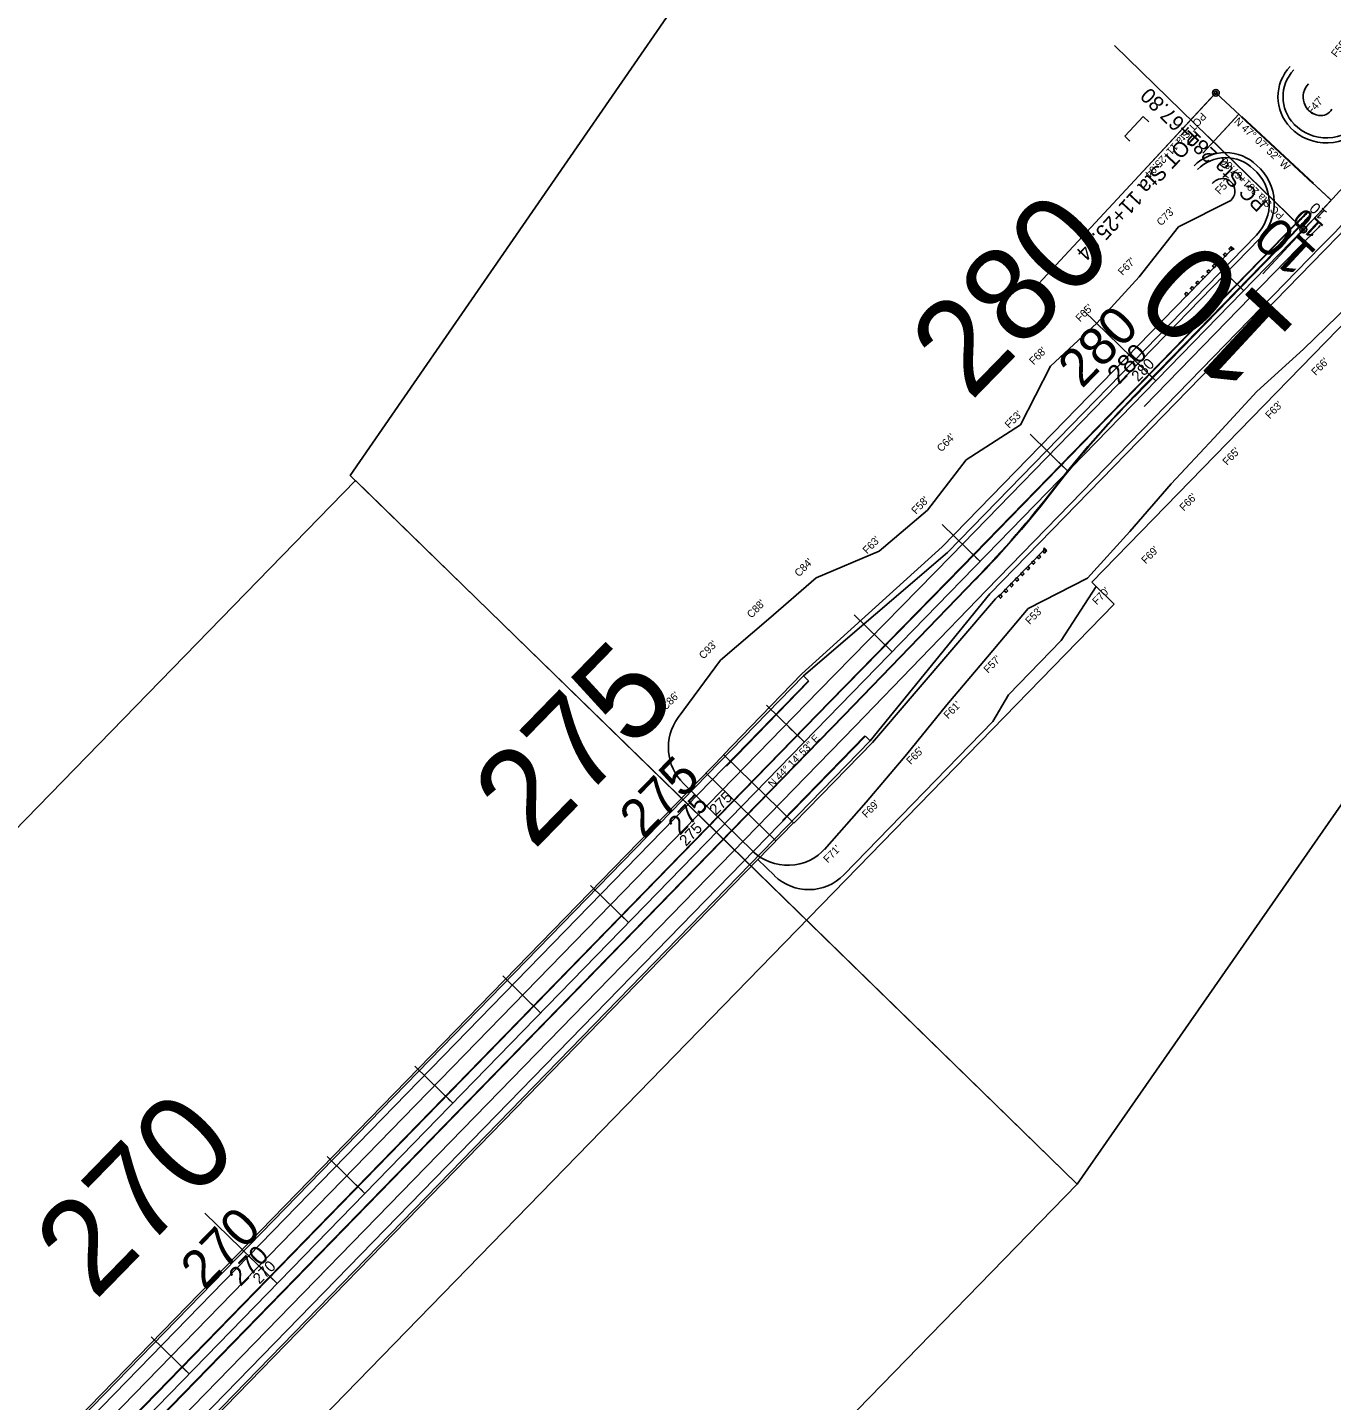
# Model space of a CAD drawing. Extents: x 2358865 to 2362945, y 393485 to 404880.
# Drawn here: x 2360577 to 2361612, y 399070 to 400160 of the extents above; entities that cross this region are included whole.
import ezdxf

# ---------------------------------------------------------------- set-up
doc = ezdxf.new("R2010")
doc.units = 0
for name, color, linetype in [('CL', 7, 'Continuous'), ('Level 11', 7, 'Continuous'), ('Level 12', 7, 'Continuous'), ('Level 19', 7, 'Continuous'), ('Level 21', 7, 'Continuous'), ('Level 25', 7, 'Continuous'), ('Level 27', 7, 'Continuous'), ('Level 28', 7, 'Continuous'), ('Level 30', 7, 'Continuous'), ('Level 33', 7, 'Continuous'), ('Level 35', 7, 'Continuous'), ('Level 36', 7, 'Continuous'), ('Level 37', 7, 'Continuous'), ('Level 39', 7, 'Continuous'), ('Level 41', 7, 'Continuous'), ('Level 48', 7, 'Continuous'), ('Level 50', 7, 'Continuous'), ('Level 51', 7, 'Continuous'), ('Level 52', 7, 'Continuous'), ('Level 53', 7, 'Continuous'), ('Level 58', 7, 'Continuous'), ('Level 59', 7, 'Continuous'), ('Level 63', 7, 'Continuous'), ('PTS-MISC', 7, 'Continuous'), ('STAEQU', 7, 'Continuous')]:
    doc.layers.add(name, color=color, linetype=linetype)

msp = doc.modelspace()

# ---------------------------------------------------------------- linework, layer by layer
at = {"layer": 'CL'}
for p, q in [((2361612.1, 400022.7), (2361520.5, 400107.8)), ((2359688.9, 398047.8), (2361589.9, 399999.4))]:
    msp.add_line(p, q, dxfattribs=at)
msp.add_arc((2360608.6, 400955.3), 1370, 315.7519, 87.327, dxfattribs=at)
at = {"layer": 'Level 11'}
for p, q in [((2361307.5, 399743.1), (2361552.7, 399994.8)), ((2361341.1, 399710.3), (2361606.8, 399983)), ((2361193.1, 399645.1), (2361307.5, 399743.1)), ((2361333.3, 399735.9), (2361333.3, 399735.9)), ((2361246.1, 399593.5), (2361341.1, 399710.3))]:
    msp.add_line(p, q, dxfattribs=at)
for centre, radius, start, end in [((2360608.6, 400955.3), 1346.5, 319.7207, 43.5046), ((2360608.6, 400955.3), 1393.5, 315.7519, 357.7915), ((2361604.8, 400104.6), 31, 136.3969, 224.1653), ((2361608.3, 400108.1), 36, 224.1653, 319.7207), ((2361528.3, 400025.4), 31, 44.7584, 135.8825), ((2361526.9, 400020), 36, 315.7519, 49.3328)]:
    msp.add_arc(centre, radius, start, end, dxfattribs=at)
at = {"layer": 'Level 12'}
for p, q in [((2361533, 399983.2), (2361498.1, 399947.4)), ((2361533, 399983.2), (2361498.1, 399947.4)), ((2361532.2, 399983.9), (2361532.7, 399985.9)), ((2361532.7, 399985.9), (2361535, 399983.8)), ((2361532.7, 399985.7), (2361534.7, 399983.7)), ((2361533, 399983.2), (2361535, 399983.8)), ((2361303.3, 399747.5), (2361498.1, 399947.4)), ((2361191.9, 399646.7), (2361303.3, 399747.5)), ((2361383.7, 399744.7), (2361348.8, 399708.9)), ((2361383.7, 399744.7), (2361348.8, 399708.9)), ((2361383.7, 399744.7), (2361384.2, 399746.8)), ((2361386.1, 399744.5), (2361384.1, 399746.5)), ((2361386.4, 399744.6), (2361384.2, 399746.8)), ((2361384.4, 399744), (2361386.4, 399744.6)), ((2361247.8, 399592.3), (2361345.6, 399706.3)), ((2361345.6, 399706.3), (2361348.4, 399709.2)), ((2361151.3, 399605), (2361191.9, 399646.7)), ((2361151.3, 399605), (2361129.5, 399582.6)), ((2361207.2, 399550.6), (2361247.8, 399592.3)), ((2361185.4, 399528.2), (2361207.2, 399550.6))]:
    msp.add_line(p, q, dxfattribs=at)
for points in [[(2361523.5, 399976.3), (2361522.1, 399974.9), (2361523.5, 399973.5), (2361524.9, 399975)], [(2361527.9, 399980.8), (2361526.5, 399979.4), (2361527.9, 399978), (2361529.3, 399979.4)], [(2361532.2, 399985.3), (2361530.8, 399983.9), (2361532.3, 399982.5), (2361533.6, 399983.9)], [(2361514.8, 399967.4), (2361513.4, 399966), (2361514.8, 399964.6), (2361516.2, 399966)], [(2361519.1, 399971.9), (2361517.7, 399970.4), (2361519.2, 399969), (2361520.6, 399970.5)], [(2361506.1, 399958.4), (2361504.7, 399957), (2361506.1, 399955.6), (2361507.5, 399957)], [(2361510.4, 399962.9), (2361509, 399961.5), (2361510.5, 399960.1), (2361511.8, 399961.5)], [(2361497.3, 399949.5), (2361495.9, 399948.1), (2361497.4, 399946.7), (2361498.8, 399948.1)], [(2361501.7, 399954), (2361500.3, 399952.5), (2361501.7, 399951.1), (2361503.1, 399952.6)], [(2361377.1, 399735.1), (2361375.7, 399733.7), (2361374.2, 399735.1), (2361375.6, 399736.5)], [(2361381.4, 399739.6), (2361380, 399738.1), (2361378.6, 399739.5), (2361380, 399741)], [(2361385.8, 399744), (2361384.4, 399742.6), (2361383, 399744), (2361384.4, 399745.4)], [(2361368.3, 399726.1), (2361366.9, 399724.7), (2361365.5, 399726.1), (2361366.9, 399727.5)], [(2361372.7, 399730.6), (2361371.3, 399729.2), (2361369.9, 399730.6), (2361371.3, 399732)], [(2361359.6, 399717.2), (2361358.2, 399715.7), (2361356.8, 399717.1), (2361358.2, 399718.6)], [(2361364, 399721.7), (2361362.6, 399720.2), (2361361.2, 399721.6), (2361362.5, 399723.1)], [(2361350.9, 399708.2), (2361349.5, 399706.8), (2361348.1, 399708.2), (2361349.5, 399709.6)], [(2361355.3, 399712.7), (2361353.9, 399711.3), (2361352.4, 399712.7), (2361353.8, 399714.1)]]:
    msp.add_lwpolyline(points, close=True, dxfattribs=at)
at = {"layer": 'Level 19'}
for p, q in [((2361310.3, 399740.3), (2361555.5, 399992.1)), ((2361338.3, 399713.1), (2361603.9, 399985.8)), ((2361205.3, 399633.2), (2361310.3, 399740.3)), ((2361234, 399605.3), (2361338.3, 399713.1)), ((2359821.6, 398212.7), (2361205.3, 399633.2)), ((2359850.3, 398184.8), (2361234, 399605.3))]:
    msp.add_line(p, q, dxfattribs=at)
for centre, radius, start, end in [((2360608.6, 400955.3), 1350.5, 319.7207, 43.5046), ((2360608.6, 400955.3), 1389.5, 315.7519, 357.7964), ((2361604.8, 400104.6), 35, 136.3969, 224.1653), ((2361608.3, 400108.1), 40, 224.1653, 319.7207), ((2361528.3, 400025.4), 35, 45.021, 135.8825), ((2361526.9, 400020), 40, 315.7519, 49.1049)]:
    msp.add_arc(centre, radius, start, end, dxfattribs=at)
at = {"layer": 'Level 25'}
for p, q in [((2361538.8, 400090.8), (2361535.4, 400087.1)), ((2361612.1, 400022.7), (2361606.7, 400016.9)), ((2361612.1, 400022.7), (2361608.4, 400026.1)), ((2361542.6, 399950.8), (2361539, 399954.3)), ((2361472.8, 399879.2), (2361467.1, 399884.8)), ((2361403.1, 399807.6), (2361399.5, 399811)), ((2361333.3, 399735.9), (2361329.7, 399739.4)), ((2361263.5, 399664.3), (2361259.9, 399667.8)), ((2361193.7, 399592.7), (2361190.1, 399596.2)), ((2361123.9, 399521), (2361118.2, 399526.6)), ((2361054.2, 399449.4), (2361050.6, 399452.9)), ((2360984.4, 399377.8), (2360980.8, 399381.3)), ((2360914.6, 399306.1), (2360911, 399309.6)), ((2360844.8, 399234.5), (2360841.3, 399238)), ((2360775.1, 399162.9), (2360769.3, 399168.4)), ((2360705.3, 399091.2), (2360701.7, 399094.7))]:
    msp.add_line(p, q, dxfattribs=at)
at = {"layer": 'Level 27'}
for p, q in [((2361448.1, 400073.5), (2361462.9, 400089)), ((2361467.2, 400084.9), (2361462.9, 400089)), ((2361452.2, 400069.5), (2361448.1, 400073.5)), ((2361421.9, 399719.4), (2361643.6, 399947.1)), ((2361439.8, 399702), (2361421.9, 399719.4)), ((2359817.5, 398036.5), (2361439.8, 399702))]:
    msp.add_line(p, q, dxfattribs=at)
at = {"layer": 'Level 28'}
for p, q in [((2361519.6, 400106.9), (2361449.3, 400031.1)), ((2361589, 400000.3), (2361514.1, 400073.3))]:
    msp.add_line(p, q, dxfattribs=at)
for centre in [(2361520.5, 400107.8), (2361589.9, 399999.4)]:
    msp.add_circle(centre, 1.25, dxfattribs=at)
at = {"layer": 'Level 30'}
for p, q in [((2361538.8, 400090.8), (2361533, 400084.5)), ((2361612.1, 400022.7), (2361601.2, 400011)), ((2361612.1, 400022.7), (2361605.9, 400028.5)), ((2361542.6, 399950.8), (2361536.5, 399956.8)), ((2361472.8, 399879.2), (2361461.4, 399890.4)), ((2361403.1, 399807.6), (2361397, 399813.5)), ((2361333.3, 399735.9), (2361327.2, 399741.9)), ((2361263.5, 399664.3), (2361257.4, 399670.2)), ((2361193.7, 399592.7), (2361187.6, 399598.6)), ((2361123.9, 399521), (2361112.5, 399532.2)), ((2361054.2, 399449.4), (2361048.1, 399455.3)), ((2360984.4, 399377.8), (2360978.3, 399383.7)), ((2360914.6, 399306.1), (2360908.5, 399312.1)), ((2360844.8, 399234.5), (2360838.8, 399240.4)), ((2360775.1, 399162.9), (2360763.6, 399174)), ((2360705.3, 399091.2), (2360699.2, 399097.2))]:
    msp.add_line(p, q, dxfattribs=at)
at = {"layer": 'Level 33'}
for p, q in [((2361588, 400001.3), (2361439.9, 400145.5)), ((2361518.6, 400105.8), (2361379.7, 399956.2))]:
    msp.add_line(p, q, dxfattribs=at)
for centre in [(2361520.5, 400107.8), (2361589.9, 399999.4)]:
    msp.add_circle(centre, 2.7, dxfattribs=at)
at = {"layer": 'Level 35'}
for p, q in [((2361205.3, 399633.2), (2361310.3, 399740.3)), ((2361234, 399605.3), (2361338.3, 399713.1)), ((2359821.6, 398212.7), (2361205.3, 399633.2)), ((2359850.3, 398184.8), (2361234, 399605.3))]:
    msp.add_line(p, q, dxfattribs=at)
at = {"layer": 'Level 36'}
msp.add_line((2361463.7, 399859), (2361594.7, 399993.6), dxfattribs=at)
msp.add_arc((2360608, 400954.8), 1377.5, 315.7519, 316.2593, dxfattribs=at)
at = {"layer": 'Level 37'}
for p, q in [((2361597.6, 400035.8), (2361540.7, 400088.7)), ((2361598, 400036.2), (2361541.1, 400089)), ((2361318.9, 399732), (2361584.5, 400004.6)), ((2361319.3, 399731.6), (2361584.9, 400004.3)), ((2361455.4, 399867), (2361587.1, 400002.2)), ((2361455.8, 399866.7), (2361587.4, 400001.8)), ((2361213.9, 399624.9), (2361318.9, 399732)), ((2361214.3, 399624.5), (2361319.3, 399731.6)), ((2361225, 399614), (2361329.3, 399721.8)), ((2361225.4, 399613.7), (2361329.7, 399721.5)), ((2359830.2, 398204.4), (2361213.9, 399624.9)), ((2359830.6, 398204), (2361214.3, 399624.5)), ((2359841.3, 398193.6), (2361225, 399614)), ((2359841.7, 398193.2), (2361225.4, 399613.7))]:
    msp.add_line(p, q, dxfattribs=at)
for centre, radius, start, end in [((2360608.6, 400955.3), 1362.5, 315.7519, 316.2264), ((2360608.6, 400955.3), 1363, 315.7519, 316.2264), ((2360608.6, 400955.3), 1366, 315.7519, 316.2264), ((2360608.6, 400955.3), 1366.5, 315.7519, 316.2264), ((2361593.8, 400011.4), 2, 316.2593, 136.2593), ((2361593.8, 400011.4), 1.5, 316.2593, 136.2593), ((2362057.5, 399280.6), 840.5, 135.7497, 142.3121), ((2362057.5, 399280.6), 840, 135.7497, 142.3121), ((2360728, 400307.6), 839.5, 315.7497, 322.3121), ((2360728, 400307.6), 840, 315.7497, 322.3121)]:
    msp.add_arc(centre, radius, start, end, dxfattribs=at)
at = {"layer": 'Level 39'}
for p, q in [((2361538.8, 400090.8), (2361527.2, 400078.3)), ((2361612.1, 400022.7), (2361599.7, 400034.3)), ((2361612.1, 400022.7), (2361590.3, 399999.3)), ((2361542.6, 399950.8), (2361530.4, 399962.7)), ((2361472.8, 399879.2), (2361449.9, 399901.5)), ((2361403.1, 399807.6), (2361390.9, 399819.4)), ((2361333.3, 399735.9), (2361321.1, 399747.8)), ((2361263.5, 399664.3), (2361251.3, 399676.2)), ((2361193.7, 399592.7), (2361181.5, 399604.5)), ((2361123.9, 399521), (2361101, 399543.4)), ((2361054.2, 399449.4), (2361042, 399461.3)), ((2360984.4, 399377.8), (2360972.2, 399389.6)), ((2360914.6, 399306.1), (2360902.4, 399318)), ((2360844.8, 399234.5), (2360832.7, 399246.4)), ((2360775.1, 399162.9), (2360752.1, 399185.2)), ((2360705.3, 399091.2), (2360693.1, 399103.1))]:
    msp.add_line(p, q, dxfattribs=at)
at = {"layer": 'Level 41'}
for p, q in [((2361538.8, 400090.8), (2361510.2, 400060)), ((2361612.1, 400022.7), (2361581.3, 400051.3)), ((2361612.1, 400022.7), (2361557.7, 399964.1)), ((2361542.6, 399950.8), (2361512.5, 399980.1)), ((2361472.8, 399879.2), (2361415.5, 399935)), ((2361403.1, 399807.6), (2361373, 399836.9)), ((2361333.3, 399735.9), (2361303.2, 399765.2)), ((2361263.5, 399664.3), (2361233.4, 399693.6)), ((2361193.7, 399592.7), (2361163.6, 399622)), ((2361123.9, 399521), (2361066.6, 399576.9)), ((2361054.2, 399449.4), (2361024.1, 399478.7)), ((2360984.4, 399377.8), (2360954.3, 399407.1)), ((2360914.6, 399306.1), (2360884.5, 399335.4)), ((2360844.8, 399234.5), (2360814.8, 399263.8)), ((2360775.1, 399162.9), (2360717.8, 399218.7)), ((2360705.3, 399091.2), (2360675.2, 399120.5))]:
    msp.add_line(p, q, dxfattribs=at)
at = {"layer": 'Level 48'}
for p, q in [((2361584.9, 400004.3), (2361319.3, 399731.6)), ((2361455.4, 399867), (2361587.1, 400002.2)), ((2361319.3, 399731.6), (2361214.3, 399624.5)), ((2361225, 399614), (2361329.3, 399721.9)), ((2361214.3, 399624.5), (2359830.6, 398204)), ((2359841.3, 398193.6), (2361225, 399614))]:
    msp.add_line(p, q, dxfattribs=at)
for centre, radius, start, end in [((2360608.6, 400955.3), 1363, 315.7516, 316.2264), ((2360608.6, 400955.3), 1366, 315.7522, 316.2264), ((2361593.8, 400011.4), 1.5, 316.2593, 136.2593), ((2362057.5, 399280.6), 840.5, 135.7497, 142.3121), ((2360728, 400307.6), 839.5, 315.7517, 322.3121)]:
    msp.add_arc(centre, radius, start, end, dxfattribs=at)
at = {"layer": 'Level 50'}
for p, q in [((2361165.4, 399690.1), (2361203.2, 399723)), ((2361127.2, 399657.5), (2361165.4, 399690.1)), ((2361093.6, 399612), (2361127.2, 399657.5))]:
    msp.add_line(p, q, dxfattribs=at)
at = {"layer": 'Level 51'}
for p, q in [((2361490.7, 400001.4), (2361532.3, 400022.5)), ((2361459.7, 399961.8), (2361490.7, 400001.4)), ((2361426, 399924.9), (2361459.7, 399961.8)), ((2361590.2, 399904.5), (2361626, 399939.4)), ((2361389.2, 399890.9), (2361426, 399924.9)), ((2361553, 399870.9), (2361590.2, 399904.5)), ((2361365.3, 399844.3), (2361389.2, 399890.9)), ((2361519.2, 399834), (2361553, 399870.9)), ((2361484.9, 399797.6), (2361519.2, 399834)), ((2361452.3, 399759.6), (2361484.9, 399797.6)), ((2361253.3, 399744.1), (2361291.5, 399776.7)), ((2361418.6, 399722.6), (2361452.3, 399759.6)), ((2361371.6, 399698.6), (2361418.6, 399722.6)), ((2361339.3, 399660.3), (2361371.6, 399698.6)), ((2361306.8, 399622.1), (2361339.3, 399660.3)), ((2361275.2, 399583.1), (2361306.8, 399622.1)), ((2361242.8, 399544.9), (2361275.2, 399583.1)), ((2361097.9, 399559.6), (2361152.7, 399506.2)), ((2361209.7, 399507.3), (2361242.8, 399544.9))]:
    msp.add_line(p, q, dxfattribs=at)
for centre, radius, start, end in [((2361604.8, 400104.6), 15, 136.3969, 259.6908), ((2361603.9, 400099.7), 10, 259.6908, 330.7019), ((2361528.3, 400025.4), 15, 119.3526, 135.8825), ((2361525.8, 400029.9), 9.87, 311.0824, 119.3083), ((2361180.6, 399534.8), 40, 225.7519, 318.5977)]:
    msp.add_arc(centre, radius, start, end, dxfattribs=at)
at = {"layer": 'Level 52'}
for p, q in [((2361322.3, 399816.5), (2361365.3, 399844.3)), ((2361291.5, 399776.7), (2361322.3, 399816.5)), ((2361203.2, 399723), (2361253.3, 399744.1))]:
    msp.add_line(p, q, dxfattribs=at)
msp.add_arc((2361125.8, 399588.3), 40, 143.5881, 225.7519, dxfattribs=at)
at = {"layer": 'Level 58'}
for p, q in [((2359947.9, 398369), (2361129.8, 399582.4)), ((2361129.8, 399582.4), (2361185.1, 399528.5)), ((2361115.8, 399568), (2361171.2, 399514.1)), ((2360003.2, 398315.1), (2361185.1, 399528.5))]:
    msp.add_line(p, q, dxfattribs=at)
at = {"layer": 'Level 59'}
for p, q in [((2361397.7, 399673.1), (2361425.4, 399716)), ((2361355.9, 399630.1), (2361397.7, 399673.1)), ((2361343.4, 399608.8), (2361355.9, 399630.1)), ((2361225.1, 399487.3), (2361343.4, 399608.8)), ((2361156.8, 399499.4), (2361170, 399486.6))]:
    msp.add_line(p, q, dxfattribs=at)
msp.add_arc((2361197.2, 399514.5), 39, 225.7519, 315.7519, dxfattribs=at)
at = {"layer": 'Level 63'}
for points in [[(2361523.4, 400803.1), (2360833.3, 399804.1), (2361123.9, 399521), (2361123.9, 399521), (2361410.5, 399241.9), (2362305.6, 400527.9), (2362344.7, 400666.9), (2362107.5, 400706.2), (2362028.4, 400719.3)], [(2360837.4, 399800.1), (2359790.8, 398725.6), (2360363.8, 398167.4), (2360363.8, 398167.4), (2361410.5, 399241.9), (2361410.5, 399241.9)]]:
    msp.add_lwpolyline(points, close=True, dxfattribs=at)
at = {"layer": 'PTS-MISC'}
for p, q in [((2361131.9, 399573.6), (2361197.4, 399640.9)), ((2361176.3, 399530.3), (2361241.9, 399597.6))]:
    msp.add_line(p, q, dxfattribs=at)
at = {"layer": 'STAEQU'}
for p, q in [((2359949, 398367.9), (2361193.1, 399645.1)), ((2361197.1, 399641.3), (2359953, 398364)), ((2361193.1, 399645.1), (2361197.1, 399641.3)), ((2359998.1, 398320.1), (2361242.2, 399597.3)), ((2361242.2, 399597.3), (2361246.1, 399593.5)), ((2361246.1, 399593.5), (2360002, 398316.2))]:
    msp.add_line(p, q, dxfattribs=at)

# ---------------------------------------------------------------- texts
at = {"layer": 'Level 21'}
for s, rotation, p in [('N 47%%d 07\' 52" W', 317.1311, (2361534.5, 400084.5)), ('N 44%%d 14\' 53" E', 45.7519, (2361168.6, 399556.1))]:
    msp.add_text(s, height=6, rotation=rotation, dxfattribs=at).set_placement(p)
at = {"layer": 'Level 25'}
for s, rotation, p in [('10', 137.1311, (2361609.4, 400012.7)), ('280', 45.7519, (2361458.8, 399878)), ('275', 45.7519, (2361123.7, 399534.1)), ('275', 45.7519, (2361099.8, 399509.5)), ('270', 45.7519, (2360761.2, 399161.9))]:
    msp.add_text(s, height=8.75, rotation=rotation, dxfattribs=at).set_placement(p)
at = {"layer": 'Level 28'}
for s, rotation, p in [('POT Sta 11+25.04', 227.1311, (2361509.2, 400092.7)), ('PC Sta 281+67.80', 135.7519, (2361575.1, 400011))]:
    msp.add_text(s, height=6, rotation=rotation, dxfattribs=at).set_placement(p)
at = {"layer": 'Level 30'}
for s, rotation, p in [('10', 137.1311, (2361607, 400002)), ('280', 45.7519, (2361443.5, 399875.8)), ('275', 45.7519, (2361094.9, 399518.1)), ('270', 45.7519, (2360746.2, 399160.1))]:
    msp.add_text(s, height=15, rotation=rotation, dxfattribs=at).set_placement(p)
at = {"layer": 'Level 33'}
for s, rotation, p in [('PC Sta 281+67.80', 135.7519, (2361562.1, 400021)), ('POT Sta 11+25.04', 227.1311, (2361499.6, 400079.4))]:
    msp.add_text(s, height=12, rotation=rotation, dxfattribs=at).set_placement(p)
at = {"layer": 'Level 39'}
for s, rotation, p in [('10', 137.1311, (2361601.8, 399981.3)), ('280', 45.7519, (2361414.1, 399872.5)), ('275', 45.7519, (2361065.9, 399515.1)), ('270', 45.7519, (2360717.4, 399157.2))]:
    msp.add_text(s, height=30, rotation=rotation, dxfattribs=at).set_placement(p)
at = {"layer": 'Level 41'}
for s, rotation, p in [('280', 45.7519, (2361325.8, 399862.3)), ('10', 137.1311, (2361586.5, 399919)), ('275', 45.7519, (2360978.7, 399505.9)), ('270', 45.7519, (2360630.6, 399148.6))]:
    msp.add_text(s, height=75, rotation=rotation, dxfattribs=at).set_placement(p)
at = {"layer": 'Level 53'}
for s, rotation, p in [("F55'", 51.2807, (2361616.1, 400135.6)), ("F47'", 49.1895, (2361596.6, 400090.1)), ("F57'", 45.7519, (2361523.5, 400026.7)), ("C73'", 45.7519, (2361477.1, 400001.8)), ("F67'", 45.7519, (2361446.4, 399962.5)), ("F65'", 45.7519, (2361412.7, 399925.6)), ("F68'", 45.7519, (2361375.9, 399891.6)), ("F66'", 45.7519, (2361599.9, 399883)), ("F63'", 45.7519, (2361563.3, 399848.7)), ("F53'", 45.7519, (2361356.5, 399841.2)), ("C64'", 45.7519, (2361302.6, 399822.4)), ("F65'", 45.7519, (2361529.4, 399811.8)), ("F58'", 45.7519, (2361282.4, 399773)), ("F66'", 45.7519, (2361495.2, 399775.5)), ("F63'", 45.7519, (2361243.7, 399741.5)), ("F69'", 45.7519, (2361464.9, 399733.6)), ("C84'", 45.7519, (2361189.6, 399723.3)), ("F70'", 45.7519, (2361426, 399701.1)), ("C88'", 45.7519, (2361151.8, 399690.5)), ("F53'", 45.7519, (2361372.8, 399685.5)), ("C93'", 45.7519, (2361113.7, 399658)), ("F57'", 45.7519, (2361339.7, 399646.9)), ("C86'", 45.7519, (2361083.7, 399617.4)), ("F61'", 45.7519, (2361307.9, 399610.6)), ("F65'", 45.7519, (2361278.3, 399574.3)), ("F69'", 45.7519, (2361243.1, 399532)), ("F71'", 45.7519, (2361212.4, 399496.3))]:
    msp.add_text(s, height=6, rotation=rotation, dxfattribs=at).set_placement(p)

doc.saveas('drawing.dxf')
